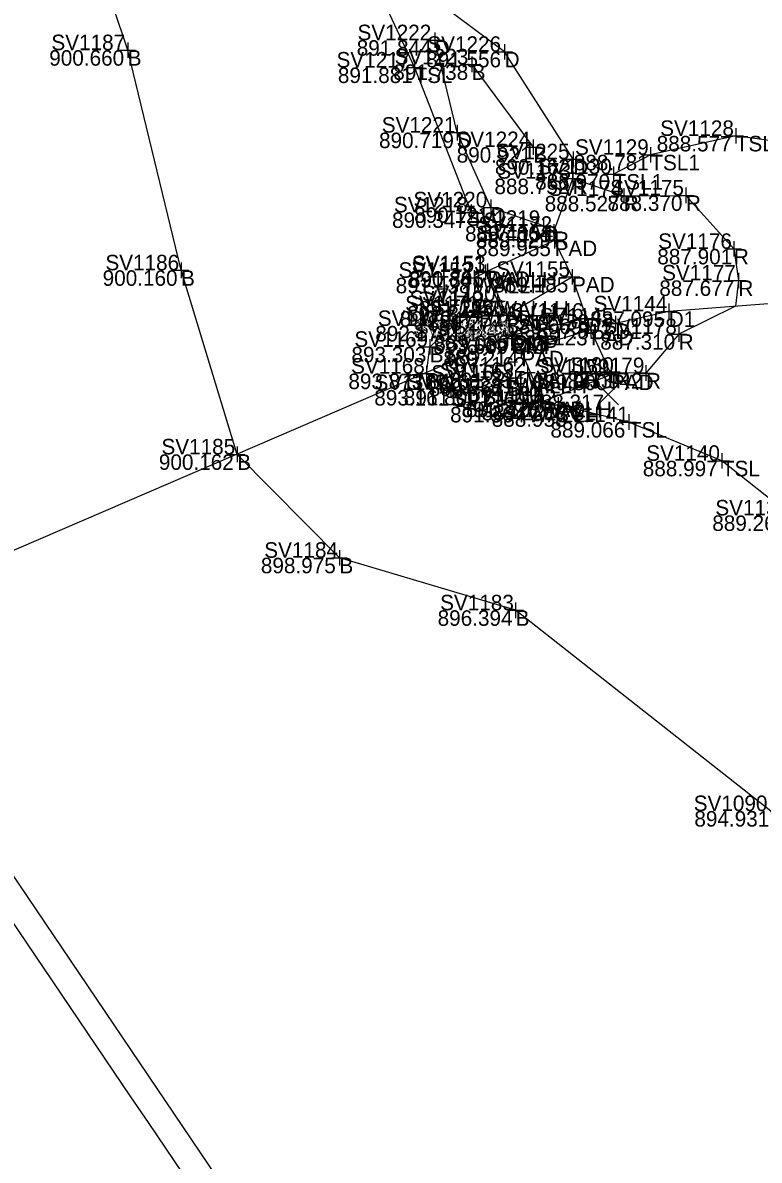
# Model space of a CAD drawing. Extents: x 1918148 to 1919797, y 624701 to 627089.
# Drawn here: x 1919000 to 1919047.5, y 625582 to 625655.4 of the extents above; entities that cross this region are included whole.
import ezdxf

# ---------------------------------------------------------------- set-up
doc = ezdxf.new("R2010")
doc.units = 0
for name, color, linetype in [('DR_X_Ditch', 7, 'Continuous'), ('DR_X_Elev_Flow', 7, 'Continuous'), ('DR_X_Erosion_Control', 7, 'Continuous'), ('DR_X_Headwall', 7, 'Continuous'), ('DR_X_Storm_Sewer', 7, 'Continuous'), ('DT_X_Break_Line', 7, 'Continuous'), ('PV_X_Shoulder_Aggregate', 7, 'Continuous'), ('SC_Scratch1', 7, 'Continuous'), ('SV_X_Break_Lines', 7, 'Continuous'), ('SV_X_Random_Point', 7, 'Continuous'), ('SV_X_Shot_Marker', 7, 'Continuous'), ('SV_X_Text_Comment', 7, 'Continuous'), ('SV_X_Text_Elevation', 7, 'Continuous'), ('SV_X_Text_Name', 7, 'Continuous'), ('SV_X_Toe_of_Slope', 7, 'Continuous'), ('SV_X_Top_of_Bank', 7, 'Continuous')]:
    doc.layers.add(name, color=color, linetype=linetype)

msp = doc.modelspace()

# ---------------------------------------------------------------- linework, layer by layer
at = {"layer": 'DR_X_Ditch'}
for points in [[(1919035.478, 625645.329), (1919035.51, 625646.582), (1919031.08, 625653.51), (1919027.02, 625656.509), (1919024.892, 625662.738), (1919022.73, 625669.421), (1919019.007, 625674.596), (1919016.395, 625677.762), (1919012.371, 625683.387), (1919005.773, 625693.451), (1919007.063, 625700.469)], [(1919034.264, 625641.9), (1919033.586, 625642.285), (1919030.182, 625643.478), (1919028.016, 625648.297), (1919026.567, 625654.26)], [(1919223.998, 625628.068), (1919215.149, 625628.647), (1919207.747, 625628.359), (1919199.304, 625627.197), (1919183.816, 625625.862), (1919165.058, 625626.669), (1919142.711, 625635.753), (1919122.833, 625635.234), (1919098.164, 625641.27), (1919077.763, 625644.248), (1919054.748, 625637.773), (1919041.672, 625636.768), (1919038.226, 625635.982), (1919036.296, 625636.302), (1919031.605, 625635.224)]]:
    msp.add_lwpolyline(points, dxfattribs=at)
at = {"layer": 'DR_X_Elev_Flow'}
for p, q in [((1919031.517, 625635.522), (1919031.517, 625634.522)), ((1919031.605, 625635.724), (1919031.605, 625634.724)), ((1919031.017, 625635.022), (1919032.017, 625635.022)), ((1919031.105, 625635.224), (1919032.105, 625635.224)), ((1919031.517, 625635.022), (1919031.517, 625635.022)), ((1919031.605, 625635.224), (1919031.605, 625635.224))]:
    msp.add_line(p, q, dxfattribs=at)
at = {"layer": 'DR_X_Erosion_Control'}
for points in [[(1919034.304, 625641.33), (1919034.264, 625641.9), (1919035.478, 625645.329), (1919038.768, 625644.216), (1919042.783, 625644.249), (1919045.874, 625640.8), (1919046.166, 625638.764), (1919045.981, 625637.099)], [(1919045.981, 625637.099), (1919042.313, 625635.3), (1919040.202, 625632.788), (1919038.247, 625632.807), (1919037.946, 625632.686)]]:
    msp.add_lwpolyline(points, dxfattribs=at)
msp.add_lwpolyline([(1919029.972, 625639.361), (1919031.21, 625636.526), (1919032.156, 625634.226), (1919033.531, 625630.954), (1919037.946, 625632.686), (1919036.65, 625635.575), (1919035.431, 625638.994), (1919034.304, 625641.33)], close=True, dxfattribs=at)
at = {"layer": 'DR_X_Headwall'}
for points in [[(1919029.11, 625638.933), (1919029.849, 625639.298), (1919030.618, 625637.428), (1919029.812, 625637.115)], [(1919031.784, 625632.476), (1919032.547, 625632.815), (1919033.404, 625630.939), (1919032.595, 625630.607)]]:
    msp.add_lwpolyline(points, close=True, dxfattribs=at)
at = {"layer": 'DR_X_Storm_Sewer'}
msp.add_line((1918912.397, 625583.966), (1919031.605, 625635.224), dxfattribs=at)
at = {"layer": 'DT_X_Break_Line'}
for p, q in [((1919031.21, 625636.526), (1919035.431, 625638.994)), ((1919036.65, 625635.575), (1919032.156, 625634.226))]:
    msp.add_line(p, q, dxfattribs=at)
at = {"layer": 'PV_X_Shoulder_Aggregate'}
msp.add_lwpolyline([(1918999.101, 625597.688), (1919000.221, 625596.032), (1919001.342, 625594.376), (1919002.463, 625592.72), (1919003.584, 625591.064), (1919004.705, 625589.408), (1919005.826, 625587.752), (1919006.947, 625586.095), (1919008.067, 625584.439), (1919009.188, 625582.783), (1919010.309, 625581.127)], dxfattribs=at)
at = {"layer": 'SV_X_Break_Lines'}
for points in [[(1919206.856, 625400.049), (1919170.289, 625439.204), (1919138.047, 625478.01), (1919112.928, 625508.775), (1919087.562, 625546.004), (1919063.33, 625584.956), (1919048.266, 625604.538), (1919031.788, 625617.486), (1919020.421, 625620.875), (1919013.825, 625627.544), (1919010.201, 625639.416), (1919006.755, 625653.616), (1919000.261, 625672.968)], [(1919028.954, 625652.7), (1919032.928, 625647.363)], [(1919031.784, 625632.476), (1919031.24, 625632.301), (1919029.639, 625631.712), (1919027.609, 625631.695), (1919026.049, 625632.755), (1919026.246, 625634.48), (1919027.775, 625635.829), (1919029.422, 625636.78), (1919029.812, 625637.115)]]:
    msp.add_lwpolyline(points, dxfattribs=at)
at = {"layer": 'SV_X_Random_Point'}
for p, q in [((1919037.105, 625630.73), (1919038.439, 625632.064)), ((1919037.105, 625632.064), (1919038.439, 625630.73)), ((1919034.639, 625629.659), (1919035.973, 625630.993)), ((1919034.639, 625630.993), (1919035.973, 625629.659))]:
    msp.add_line(p, q, dxfattribs=at)
at = {"layer": 'SV_X_Shot_Marker'}
for p, q in [((1919026.567, 625654.76), (1919026.567, 625653.76)), ((1919006.755, 625654.116), (1919006.755, 625653.116)), ((1919026.067, 625654.26), (1919027.067, 625654.26)), ((1919026.567, 625654.26), (1919026.567, 625654.26)), ((1919031.08, 625654.01), (1919031.08, 625653.01)), ((1919006.255, 625653.616), (1919007.255, 625653.616)), ((1919006.755, 625653.616), (1919006.755, 625653.616)), ((1919028.954, 625653.2), (1919028.954, 625652.2)), ((1919030.58, 625653.51), (1919031.58, 625653.51)), ((1919031.08, 625653.51), (1919031.08, 625653.51)), ((1919024.761, 625652.497), (1919025.761, 625652.497)), ((1919025.261, 625652.997), (1919025.261, 625651.997)), ((1919025.261, 625652.497), (1919025.261, 625652.497)), ((1919028.454, 625652.7), (1919029.454, 625652.7)), ((1919028.954, 625652.7), (1919028.954, 625652.7)), ((1919028.016, 625648.797), (1919028.016, 625647.797)), ((1919027.516, 625648.297), (1919028.516, 625648.297)), ((1919028.016, 625648.297), (1919028.016, 625648.297)), ((1919045.498, 625648.086), (1919046.498, 625648.086)), ((1919045.998, 625648.586), (1919045.998, 625647.586)), ((1919045.998, 625648.086), (1919045.998, 625648.086)), ((1919032.428, 625647.363), (1919033.428, 625647.363)), ((1919032.928, 625647.863), (1919032.928, 625646.863)), ((1919032.928, 625647.363), (1919032.928, 625647.363)), ((1919040.484, 625647.366), (1919040.484, 625646.366)), ((1919035.01, 625646.582), (1919036.01, 625646.582)), ((1919035.51, 625647.082), (1919035.51, 625646.082)), ((1919035.51, 625646.582), (1919035.51, 625646.582)), ((1919039.984, 625646.866), (1919040.984, 625646.866)), ((1919040.484, 625646.866), (1919040.484, 625646.866)), ((1919035.478, 625645.829), (1919035.478, 625644.829)), ((1919038.115, 625646.12), (1919038.115, 625645.12)), ((1919034.978, 625645.329), (1919035.978, 625645.329)), ((1919035.478, 625645.329), (1919035.478, 625645.329)), ((1919037.615, 625645.62), (1919038.615, 625645.62)), ((1919038.115, 625645.62), (1919038.115, 625645.62)), ((1919038.268, 625644.216), (1919039.268, 625644.216)), ((1919038.768, 625644.716), (1919038.768, 625643.716)), ((1919038.768, 625644.216), (1919038.768, 625644.216)), ((1919042.283, 625644.249), (1919043.283, 625644.249)), ((1919042.783, 625644.749), (1919042.783, 625643.749)), ((1919042.783, 625644.249), (1919042.783, 625644.249)), ((1919028.918, 625643.654), (1919028.918, 625642.654)), ((1919030.182, 625643.978), (1919030.182, 625642.978)), ((1919028.418, 625643.154), (1919029.418, 625643.154)), ((1919028.918, 625643.154), (1919028.918, 625643.154)), ((1919029.682, 625643.478), (1919030.682, 625643.478)), ((1919030.182, 625643.478), (1919030.182, 625643.478)), ((1919033.586, 625642.785), (1919033.586, 625641.785)), ((1919033.086, 625642.285), (1919034.086, 625642.285)), ((1919033.586, 625642.285), (1919033.586, 625642.285)), ((1919034.264, 625642.4), (1919034.264, 625641.4)), ((1919033.764, 625641.9), (1919034.764, 625641.9)), ((1919033.804, 625641.33), (1919034.804, 625641.33)), ((1919034.264, 625641.9), (1919034.264, 625641.9)), ((1919034.304, 625641.83), (1919034.304, 625640.83)), ((1919034.304, 625641.33), (1919034.304, 625641.33)), ((1919045.874, 625641.3), (1919045.874, 625640.3)), ((1919045.374, 625640.8), (1919046.374, 625640.8)), ((1919045.874, 625640.8), (1919045.874, 625640.8)), ((1919010.201, 625639.916), (1919010.201, 625638.916)), ((1919029.972, 625639.861), (1919029.972, 625638.861)), ((1919009.701, 625639.416), (1919010.701, 625639.416)), ((1919010.201, 625639.416), (1919010.201, 625639.416)), ((1919029.11, 625639.433), (1919029.11, 625638.433)), ((1919029.349, 625639.298), (1919030.349, 625639.298)), ((1919029.472, 625639.361), (1919030.472, 625639.361)), ((1919029.849, 625639.798), (1919029.849, 625638.798)), ((1919029.849, 625639.298), (1919029.849, 625639.298)), ((1919029.972, 625639.361), (1919029.972, 625639.361)), ((1919035.431, 625639.494), (1919035.431, 625638.494)), ((1919046.166, 625639.264), (1919046.166, 625638.264)), ((1919028.61, 625638.933), (1919029.61, 625638.933)), ((1919029.11, 625638.933), (1919029.11, 625638.933)), ((1919034.931, 625638.994), (1919035.931, 625638.994)), ((1919035.431, 625638.994), (1919035.431, 625638.994)), ((1919045.666, 625638.764), (1919046.666, 625638.764)), ((1919046.166, 625638.764), (1919046.166, 625638.764)), ((1919029.812, 625637.615), (1919029.812, 625636.615)), ((1919030.618, 625637.928), (1919030.618, 625636.928)), ((1919029.312, 625637.115), (1919030.312, 625637.115)), ((1919029.422, 625637.28), (1919029.422, 625636.28)), ((1919029.812, 625637.115), (1919029.812, 625637.115)), ((1919030.118, 625637.428), (1919031.118, 625637.428)), ((1919030.618, 625637.428), (1919030.618, 625637.428)), ((1919031.21, 625637.026), (1919031.21, 625636.026)), ((1919041.672, 625637.268), (1919041.672, 625636.268)), ((1919027.775, 625636.329), (1919027.775, 625635.329)), ((1919028.922, 625636.78), (1919029.922, 625636.78)), ((1919029.422, 625636.78), (1919029.422, 625636.78)), ((1919030.71, 625636.526), (1919031.71, 625636.526)), ((1919031.21, 625636.526), (1919031.21, 625636.526)), ((1919035.796, 625636.302), (1919036.796, 625636.302)), ((1919036.296, 625636.802), (1919036.296, 625635.802)), ((1919036.296, 625636.302), (1919036.296, 625636.302)), ((1919038.226, 625636.482), (1919038.226, 625635.482)), ((1919041.172, 625636.768), (1919042.172, 625636.768)), ((1919041.672, 625636.768), (1919041.672, 625636.768)), ((1919027.275, 625635.829), (1919028.275, 625635.829)), ((1919027.775, 625635.829), (1919027.775, 625635.829)), ((1919031.517, 625635.522), (1919031.517, 625634.522)), ((1919031.605, 625635.724), (1919031.605, 625634.724)), ((1919031.605, 625635.724), (1919031.605, 625634.724)), ((1919036.15, 625635.575), (1919037.15, 625635.575)), ((1919036.65, 625636.075), (1919036.65, 625635.075)), ((1919036.65, 625635.575), (1919036.65, 625635.575)), ((1919037.726, 625635.982), (1919038.726, 625635.982)), ((1919038.226, 625635.982), (1919038.226, 625635.982)), ((1919042.313, 625635.8), (1919042.313, 625634.8)), ((1919026.246, 625634.98), (1919026.246, 625633.98)), ((1919031.017, 625635.022), (1919032.017, 625635.022)), ((1919031.105, 625635.224), (1919032.105, 625635.224)), ((1919031.105, 625635.224), (1919032.105, 625635.224)), ((1919031.517, 625635.022), (1919031.517, 625635.022)), ((1919031.605, 625635.224), (1919031.605, 625635.224)), ((1919031.605, 625635.224), (1919031.605, 625635.224)), ((1919032.156, 625634.726), (1919032.156, 625633.726)), ((1919041.813, 625635.3), (1919042.813, 625635.3)), ((1919042.313, 625635.3), (1919042.313, 625635.3)), ((1919025.746, 625634.48), (1919026.746, 625634.48)), ((1919026.246, 625634.48), (1919026.246, 625634.48)), ((1919031.656, 625634.226), (1919032.656, 625634.226)), ((1919032.156, 625634.226), (1919032.156, 625634.226)), ((1919026.049, 625633.255), (1919026.049, 625632.255)), ((1919032.547, 625633.315), (1919032.547, 625632.315)), ((1919038.247, 625633.307), (1919038.247, 625632.307)), ((1919040.202, 625633.288), (1919040.202, 625632.288)), ((1919025.549, 625632.755), (1919026.549, 625632.755)), ((1919026.049, 625632.755), (1919026.049, 625632.755)), ((1919031.24, 625632.801), (1919031.24, 625631.801)), ((1919031.784, 625632.976), (1919031.784, 625631.976)), ((1919032.047, 625632.815), (1919033.047, 625632.815)), ((1919032.547, 625632.815), (1919032.547, 625632.815)), ((1919037.446, 625632.686), (1919038.446, 625632.686)), ((1919037.747, 625632.807), (1919038.747, 625632.807)), ((1919037.946, 625633.186), (1919037.946, 625632.186)), ((1919037.946, 625632.686), (1919037.946, 625632.686)), ((1919038.247, 625632.807), (1919038.247, 625632.807)), ((1919039.702, 625632.788), (1919040.702, 625632.788)), ((1919040.202, 625632.788), (1919040.202, 625632.788)), ((1919027.609, 625632.195), (1919027.609, 625631.195)), ((1919029.639, 625632.212), (1919029.639, 625631.212)), ((1919030.74, 625632.301), (1919031.74, 625632.301)), ((1919031.24, 625632.301), (1919031.24, 625632.301)), ((1919031.284, 625632.476), (1919032.284, 625632.476)), ((1919031.784, 625632.476), (1919031.784, 625632.476)), ((1919027.109, 625631.695), (1919028.109, 625631.695)), ((1919027.609, 625631.695), (1919027.609, 625631.695)), ((1919029.139, 625631.712), (1919030.139, 625631.712)), ((1919029.639, 625631.712), (1919029.639, 625631.712)), ((1919032.595, 625631.107), (1919032.595, 625630.107)), ((1919033.404, 625631.439), (1919033.404, 625630.439)), ((1919033.531, 625631.454), (1919033.531, 625630.454)), ((1919034.535, 625631.234), (1919034.535, 625630.234)), ((1919032.095, 625630.607), (1919033.095, 625630.607)), ((1919032.595, 625630.607), (1919032.595, 625630.607)), ((1919032.904, 625630.939), (1919033.904, 625630.939)), ((1919033.031, 625630.954), (1919034.031, 625630.954)), ((1919033.404, 625630.939), (1919033.404, 625630.939)), ((1919033.531, 625630.954), (1919033.531, 625630.954)), ((1919034.035, 625630.734), (1919035.035, 625630.734)), ((1919034.535, 625630.734), (1919034.535, 625630.734)), ((1919038.6, 625629.627), (1919039.6, 625629.627)), ((1919039.1, 625630.127), (1919039.1, 625629.127)), ((1919039.1, 625629.627), (1919039.1, 625629.627)), ((1919013.325, 625627.544), (1919014.325, 625627.544)), ((1919013.825, 625628.044), (1919013.825, 625627.044)), ((1919013.825, 625627.544), (1919013.825, 625627.544)), ((1919045.099, 625627.629), (1919045.099, 625626.629)), ((1919044.599, 625627.129), (1919045.599, 625627.129)), ((1919045.099, 625627.129), (1919045.099, 625627.129)), ((1919019.921, 625620.875), (1919020.921, 625620.875)), ((1919020.421, 625621.375), (1919020.421, 625620.375)), ((1919020.421, 625620.875), (1919020.421, 625620.875)), ((1919031.788, 625617.986), (1919031.788, 625616.986)), ((1919031.288, 625617.486), (1919032.288, 625617.486)), ((1919031.788, 625617.486), (1919031.788, 625617.486))]:
    msp.add_line(p, q, dxfattribs=at)
at = {"layer": 'SV_X_Toe_of_Slope'}
for points in [[(1919144.348, 625769.585), (1919100.267, 625767.867), (1919060.949, 625770.926), (1919021.621, 625778.27), (1918998.317, 625779.772), (1918985.024, 625778.226), (1918981.125, 625762.931), (1918979.642, 625746.599), (1918992.24, 625715.177), (1919001.076, 625693.545), (1919008.188, 625681.542), (1919013.947, 625671.921), (1919018.788, 625665.983), (1919022.164, 625659.123), (1919025.261, 625652.497), (1919028.918, 625643.154)], [(1919201.205, 625630.948), (1919184.187, 625629.739), (1919164.633, 625631.139), (1919143.852, 625641.12), (1919121.904, 625641.817), (1919098.949, 625646.437), (1919070.565, 625648.436), (1919055.291, 625646.772), (1919045.998, 625648.086), (1919040.484, 625646.866), (1919038.115, 625645.62)], [(1919201.69, 625623.474), (1919183.292, 625622.304), (1919164.815, 625624.12), (1919141.222, 625629.5), (1919122.464, 625631.746), (1919096.929, 625636.647), (1919075.894, 625635.335), (1919063.894, 625633.35), (1919057.91, 625628.429), (1919056.849, 625624.757), (1919055.856, 625621.448), (1919055.54, 625619.908), (1919054.713, 625619.178), (1919053.992, 625619.561), (1919053.17, 625621.205), (1919049.54, 625623.605), (1919045.099, 625627.129), (1919039.1, 625629.627), (1919034.535, 625630.734)]]:
    msp.add_lwpolyline(points, dxfattribs=at)
at = {"layer": 'SV_X_Top_of_Bank'}
msp.add_lwpolyline([(1919180.035, 625377.767), (1919142.39, 625420.85), (1919113.902, 625458.171), (1919086.603, 625489.422), (1919057.387, 625523.08), (1919019.76, 625570.221), (1918998.067, 625602.274), (1918985.265, 625627.561), (1918968.388, 625668.032), (1918955.62, 625707.629), (1918947.904, 625739.173), (1918945.039, 625765.587), (1918947.372, 625785.939), (1918957.935, 625802.753), (1918975.613, 625809.208), (1918997.576, 625813.393), (1919030.667, 625814.442), (1919065.449, 625812.352), (1919111.287, 625808.541)], dxfattribs=at)

# ---------------------------------------------------------------- texts
at = {"layer": 'SC_Scratch1'}
msp.add_text("889.05'", height=1, rotation=23.26712, dxfattribs=at).set_placement((1919027.578, 625632.948))
at = {"layer": 'SV_X_Text_Comment'}
for s, p in [('D', (1919026.567, 625653.26)), ('B', (1919006.755, 625652.616)), ('D', (1919031.08, 625652.51)), ('TSL', (1919025.261, 625651.497)), ('B', (1919028.954, 625651.7)), ('D', (1919028.016, 625647.297)), ('TSL1', (1919045.998, 625647.086)), ('B', (1919032.928, 625646.363)), ('D', (1919035.51, 625645.582)), ('TSL1', (1919040.484, 625645.866)), ('R', (1919035.478, 625644.329)), ('TSL1', (1919038.115, 625644.62)), ('R', (1919038.768, 625643.216)), ('R', (1919042.783, 625643.249)), ('TSL', (1919028.918, 625642.154)), ('D', (1919030.182, 625642.478)), ('D', (1919033.586, 625641.285)), ('R', (1919034.264, 625640.9)), ('PAD', (1919034.304, 625640.33)), ('R', (1919045.874, 625639.8)), ('B', (1919010.201, 625638.416)), ('WALLH', (1919029.849, 625638.298)), ('PAD', (1919029.972, 625638.361)), ('WALLH', (1919029.11, 625637.933)), ('PAD', (1919035.431, 625637.994)), ('R', (1919046.166, 625637.764)), ('WALLH', (1919029.812, 625636.115)), ('WALLH', (1919030.618, 625636.428)), ('B1', (1919029.422, 625635.78)), ('PAD', (1919031.21, 625635.526)), ('D1', (1919036.296, 625635.302)), ('D1', (1919041.672, 625635.768)), ('B1', (1919027.775, 625634.829)), ('PAD', (1919036.65, 625634.575)), ('D1', (1919038.226, 625634.982)), ('CMP', (1919031.517, 625634.022)), ('PIO', (1919031.517, 625634.022)), ('CMP', (1919031.605, 625634.224)), ('PIO', (1919031.605, 625634.224)), ('D1', (1919031.605, 625634.224)), ('R', (1919042.313, 625634.3)), ('B1', (1919026.246, 625633.48)), ('PAD', (1919032.156, 625633.226)), ('B1', (1919026.049, 625631.755)), ('WALLH', (1919032.547, 625631.815)), ('PAD', (1919037.946, 625631.686)), ('R', (1919038.247, 625631.807)), ('R', (1919040.202, 625631.788)), ('B1', (1919031.24, 625631.301)), ('WALLH', (1919031.784, 625631.476)), ('B1', (1919027.609, 625630.695)), ('B1', (1919029.639, 625630.712)), ('WALLH', (1919032.595, 625629.607)), ('WALLH', (1919033.404, 625629.939)), ('PAD', (1919033.531, 625629.954)), ('TSL', (1919034.535, 625629.734)), ('TSL', (1919039.1, 625628.627)), ('B', (1919013.825, 625626.544)), ('TSL', (1919045.099, 625626.129)), ('B', (1919020.421, 625619.875)), ('B', (1919031.788, 625616.486))]:
    msp.add_text(s, height=1, dxfattribs=at).set_placement(p)
at = {"layer": 'SV_X_Text_Elevation'}
for s, p in [('891.844', (1919021.536, 625653.26)), ('900.660', (1919001.694, 625652.616)), ('891.556', (1919026.016, 625652.51)), ('891.881', (1919020.32, 625651.497)), ('891.738', (1919023.895, 625651.7)), ('890.719', (1919022.975, 625647.297)), ('888.577', (1919040.895, 625647.086)), ('890.921', (1919027.987, 625646.363)), ('890.162', (1919030.454, 625645.582)), ('888.781', (1919035.543, 625645.866)), ('888.752', (1919030.422, 625644.329)), ('888.970', (1919033.054, 625644.62)), ('888.527', (1919033.665, 625643.216)), ('888.370', (1919037.722, 625643.249)), ('890.121', (1919025.241, 625642.478)), ('890.347', (1919023.815, 625642.154)), ('889.400', (1919028.525, 625641.285)), ('889.029', (1919029.223, 625640.9)), ('889.955', (1919029.233, 625640.33)), ('887.901', (1919040.933, 625639.8)), ('900.160', (1919005.14, 625638.416)), ('890.805', (1919024.901, 625638.361)), ('891.341', (1919024.908, 625638.298)), ('891.438', (1919024.051, 625637.933)), ('889.185', (1919030.36, 625637.994)), ('887.677', (1919041.063, 625637.764)), ('891.344', (1919024.781, 625636.115)), ('891.298', (1919025.559, 625636.428)), ('890.947', (1919024.319, 625635.78)), ('889.277', (1919026.107, 625635.526)), ('889.069', (1919031.255, 625635.302)), ('887.095', (1919036.601, 625635.768)), ('892.179', (1919022.734, 625634.829)), ('889.123', (1919031.6, 625634.575)), ('887.813', (1919033.176, 625634.982)), ('893.669', (1919026.476, 625634.022)), ('893.669', (1919026.476, 625634.022)), ('889.050', (1919026.544, 625634.224)), ('889.050', (1919026.544, 625634.224)), ('889.050', (1919026.544, 625634.224)), ('887.310', (1919037.252, 625634.3)), ('893.303', (1919021.196, 625633.48)), ('889.214', (1919027.125, 625633.226)), ('893.873', (1919020.999, 625631.755)), ('891.381', (1919026.843, 625631.476)), ('891.334', (1919027.516, 625631.815)), ('889.800', (1919032.885, 625631.686)), ('887.733', (1919033.197, 625631.807)), ('887.942', (1919035.146, 625631.788)), ('890.762', (1919026.184, 625631.301)), ('893.161', (1919022.668, 625630.695)), ('891.800', (1919024.578, 625630.712)), ('888.317', (1919032.669, 625630.397)), ('891.364', (1919027.564, 625629.607)), ('891.297', (1919028.301, 625629.939)), ('890.721', (1919028.59, 625629.954)), ('889.221', (1919029.594, 625629.734)), ('888.958', (1919030.247, 625629.326)), ('889.066', (1919034.036, 625628.627)), ('900.162', (1919008.769, 625626.544)), ('888.997', (1919039.996, 625626.129)), ('889.268', (1919044.481, 625622.605)), ('898.975', (1919015.35, 625619.875)), ('896.394', (1919026.757, 625616.486)), ('894.931', (1919043.325, 625603.538))]:
    msp.add_text(s, height=1, dxfattribs=at).set_placement(p)
at = {"layer": 'SV_X_Text_Name'}
for s, p in [('SV1222', (1919021.588, 625654.26)), ('SV1187', (1919001.833, 625653.616)), ('SV1226', (1919026.093, 625653.51)), ('SV1217', (1919020.235, 625652.497)), ('SV1223', (1919023.981, 625652.7)), ('SV1221', (1919023.152, 625648.297)), ('SV1128', (1919041.119, 625648.086)), ('SV1224', (1919027.974, 625647.363)), ('SV1225', (1919030.516, 625646.582)), ('SV1129', (1919035.623, 625646.866)), ('SV1130', (1919033.235, 625645.62)), ('SV1173', (1919030.609, 625645.329)), ('SV1174', (1919033.917, 625644.216)), ('SV1175', (1919037.893, 625644.249)), ('SV1220', (1919025.198, 625643.478)), ('SV1218', (1919023.936, 625643.154)), ('SV1219', (1919028.622, 625642.285)), ('SV1172', (1919029.388, 625641.9)), ('SV1154', (1919029.453, 625641.33)), ('SV1176', (1919040.991, 625640.8)), ('SV1186', (1919005.318, 625639.416)), ('SV1152', (1919024.234, 625638.933)), ('SV1151', (1919025.089, 625639.298)), ('SV1153', (1919025.103, 625639.361)), ('SV1155', (1919030.541, 625638.994)), ('SV1177', (1919041.244, 625638.764)), ('SV1150', (1919025.738, 625637.428)), ('SV1171', (1919024.662, 625636.78)), ('SV1149', (1919024.951, 625637.115)), ('SV1144', (1919036.821, 625636.768)), ('SV1156', (1919026.327, 625636.526)), ('SV1146', (1919031.413, 625636.302)), ('SV1145', (1919033.336, 625635.982)), ('SV1170', (1919022.895, 625635.829)), ('SV1147_2', (1919025.176, 625635.224)), ('SV1147_1', (1919025.292, 625635.224)), ('SV1147', (1919026.683, 625635.224)), ('SV1158', (1919031.771, 625635.575)), ('SV1178', (1919037.434, 625635.3)), ('SV1169', (1919021.385, 625634.48)), ('SV1148_1', (1919025.204, 625635.022)), ('SV1148', (1919026.638, 625635.022)), ('SV1157', (1919027.234, 625634.226)), ('SV1168', (1919021.17, 625632.755)), ('SV1165', (1919026.35, 625632.301)), ('SV1163', (1919026.915, 625632.476)), ('SV1162', (1919027.671, 625632.815)), ('SV1159', (1919033.085, 625632.686)), ('SV1180', (1919033.367, 625632.807)), ('SV1179', (1919035.341, 625632.788)), ('SV1167', (1919022.687, 625631.695)), ('SV1166', (1919024.756, 625631.712)), ('SV1161', (1919028.644, 625630.939)), ('SV1160', (1919028.651, 625630.954)), ('SV1142', (1919029.659, 625630.734)), ('SV1164', (1919027.744, 625630.607)), ('SV1141', (1919034.34, 625629.627)), ('SV1185', (1919008.935, 625627.544)), ('SV1140', (1919040.219, 625627.129)), ('SV1139', (1919044.679, 625623.605)), ('SV1184', (1919015.57, 625620.875)), ('SV1183', (1919026.919, 625617.486)), ('SV1090', (1919043.282, 625604.538))]:
    msp.add_text(s, height=1, dxfattribs=at).set_placement(p)

doc.saveas('drawing.dxf')
